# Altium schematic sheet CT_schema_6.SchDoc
size 287 x 243 mm
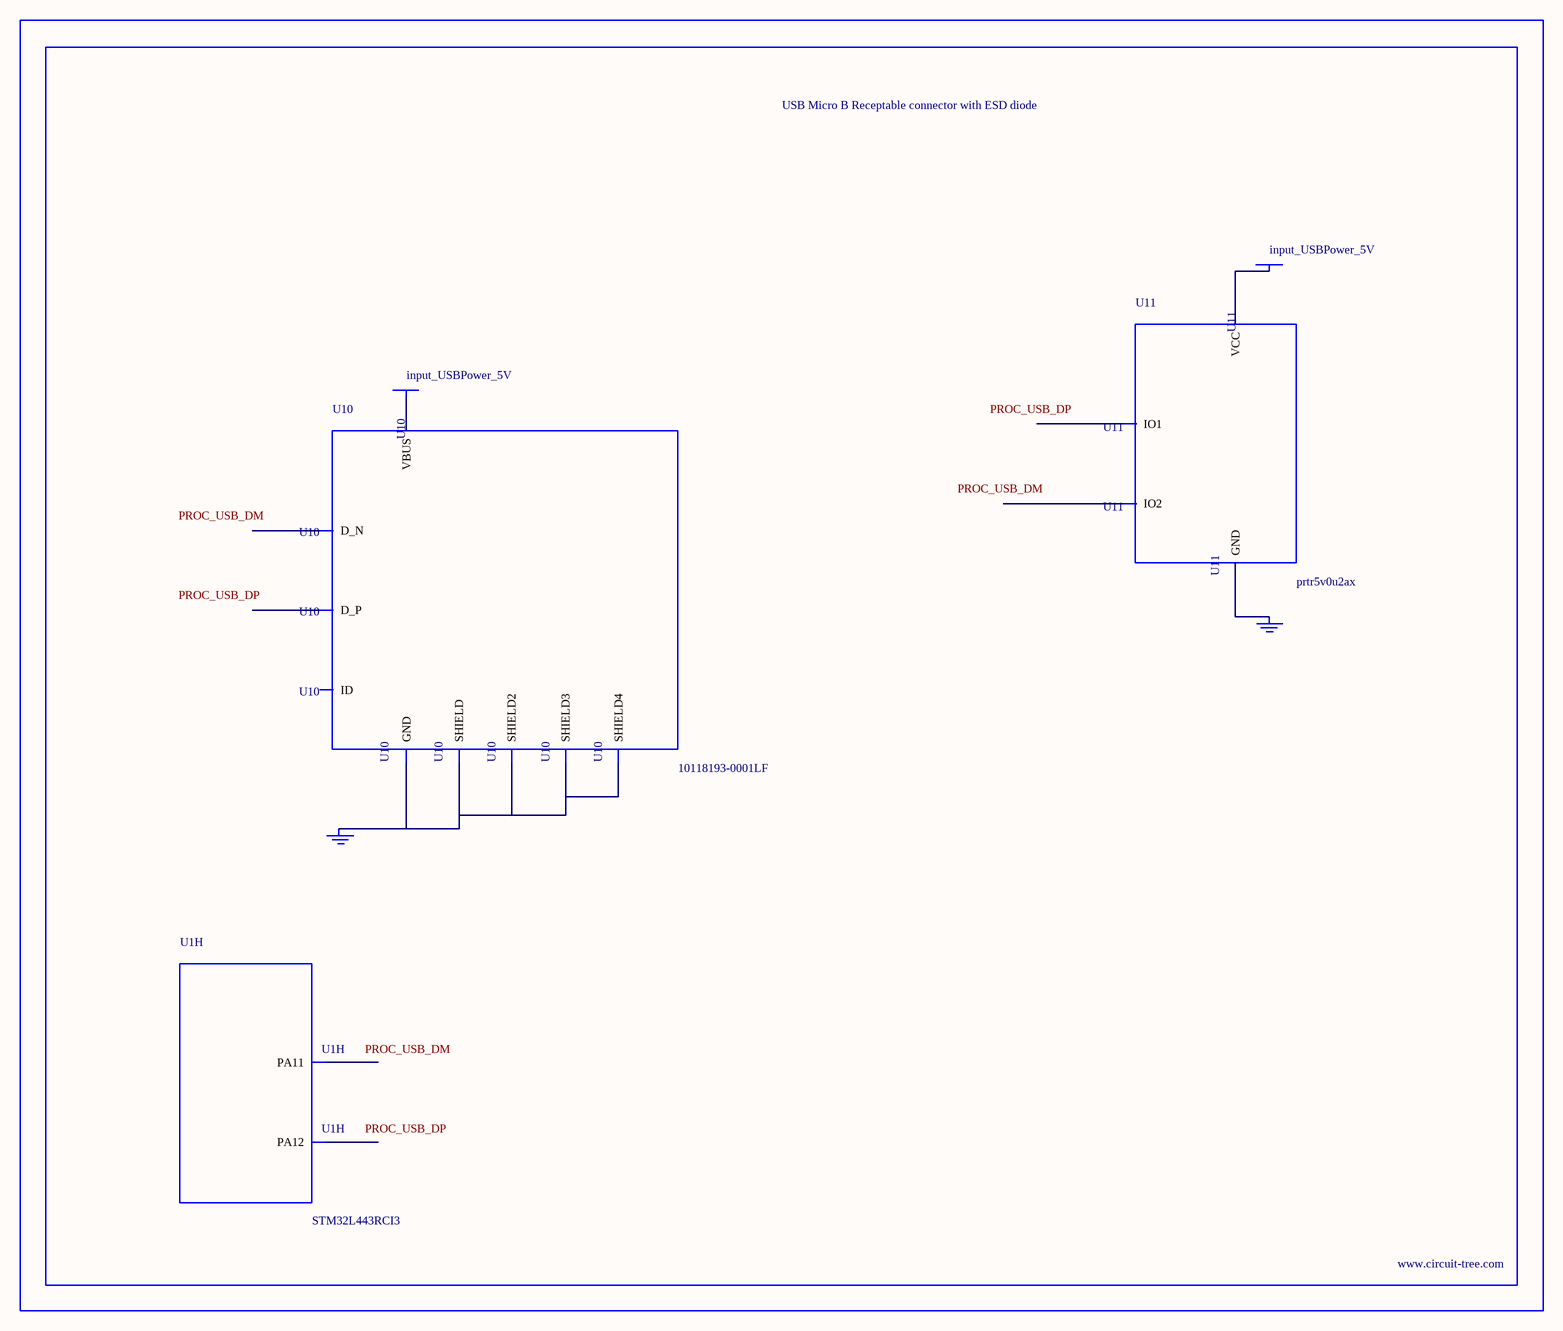
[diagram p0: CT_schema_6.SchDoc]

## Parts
BORDER5  (no value)
GND_INSTANCE_5_0  (no value)
GND_INSTANCE_5_1  (no value)
POWER_INSTANCE_5_0  input_USBPower_5V
POWER_INSTANCE_5_1  input_USBPower_5V
U1  STM32L443RCI3  [UFBGA64]  (part H of 8)
U10  10118193-0001LF  [FCI_10118193-0001LF]
U11  prtr5v0u2ax  [SOT143B]

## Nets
NetGND_INSTANCE_5_0_0: GND_INSTANCE_5_0.0(GND) U10.5(GND) U10.6(SHIELD) U10.7(SHIELD2) U10.8(SHIELD3) U10.9(SHIELD4)
NetGND_INSTANCE_5_1_0: GND_INSTANCE_5_1.0(GND) U11.1(GND)
NetPOWER_INSTANCE_5_0_0: POWER_INSTANCE_5_0.0(PWR) U10.1(VBUS)
NetPOWER_INSTANCE_5_1_0: POWER_INSTANCE_5_1.0(PWR) U11.4(VCC)

Not connected (* = marked no-connect by the designer): U1 B8(PA12) C8(PA11); U10 2(D_N) 3(D_P) 4(ID); U11 2(IO1) 3(IO2)

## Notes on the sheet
- Labels drawn without touching a wire or pin: PROC_USB_DM, PROC_USB_DP

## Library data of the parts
BORDER5 = BORDER_PAGE5
GND_INSTANCE_5_0 GND_INSTANCE_5_1 = GND
POWER_INSTANCE_5_0 POWER_INSTANCE_5_1 = PWR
